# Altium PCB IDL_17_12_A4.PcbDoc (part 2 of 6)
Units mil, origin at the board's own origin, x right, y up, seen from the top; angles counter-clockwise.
Board outline 3172.06 x 10350 mil, 6 copper layers (Top Signal, Mid Signal, 3.3 Volt, GND, 5 Volt, Bot Signal), stack 122.8 mil thick; 332 components, 120 nets, 1937 pads, 197 vias.
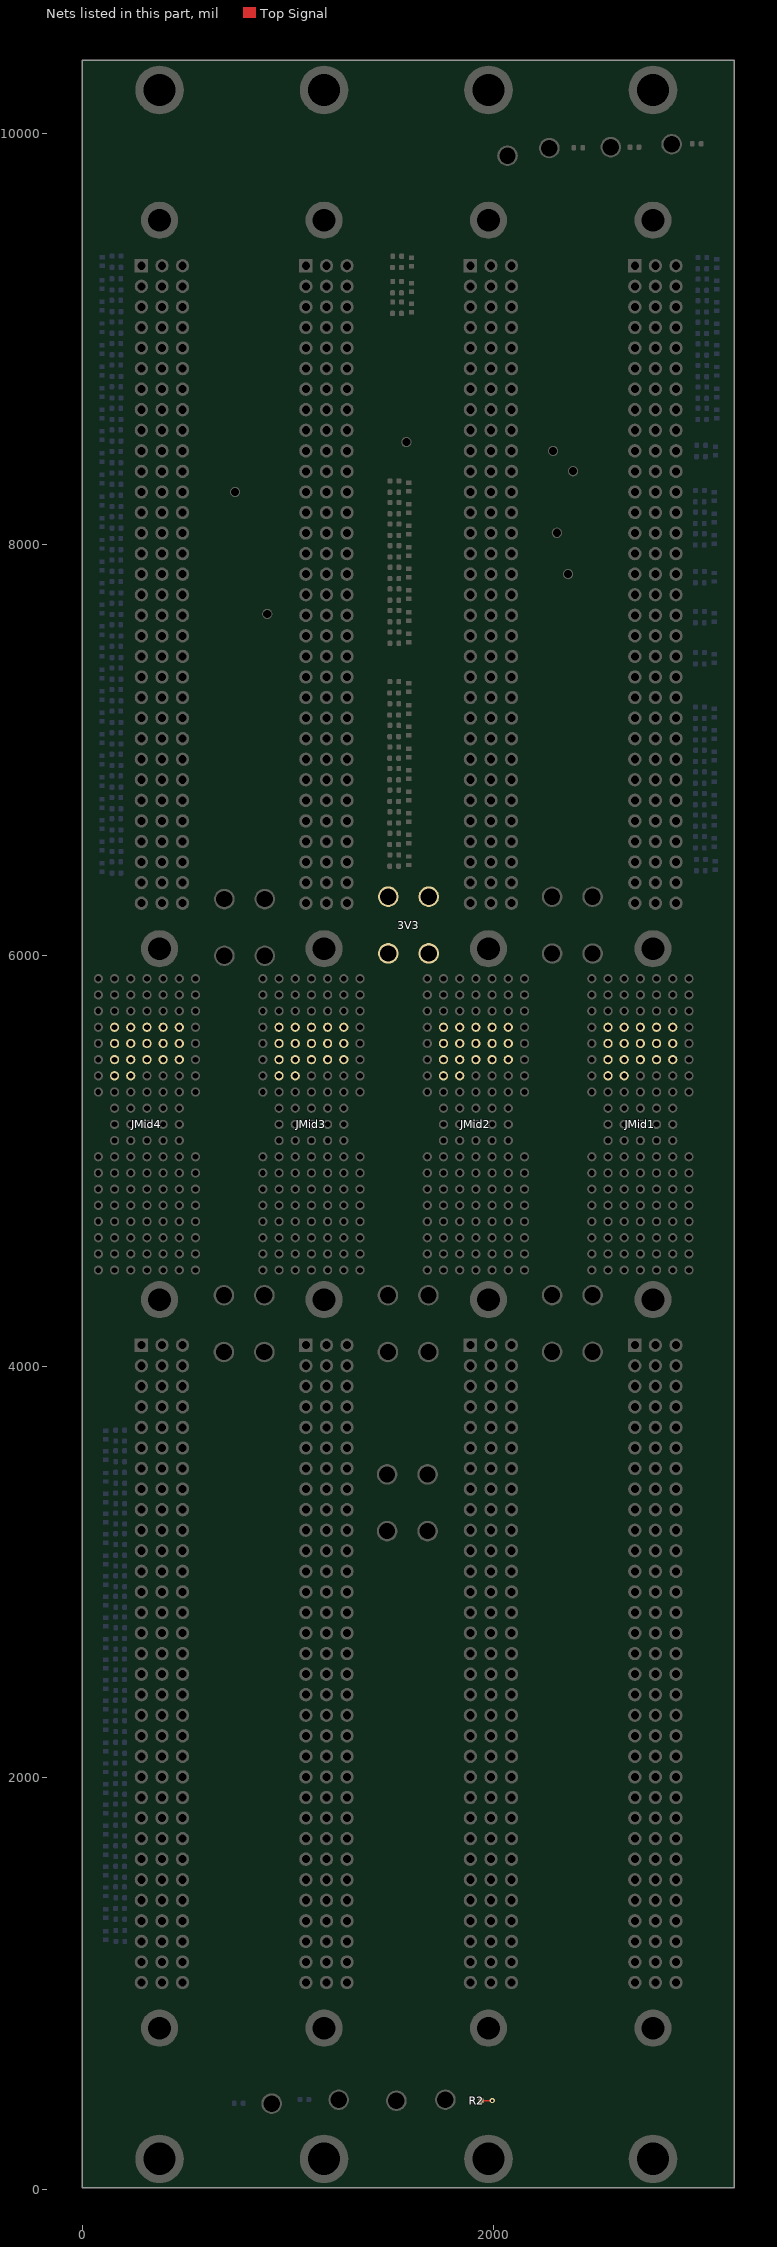
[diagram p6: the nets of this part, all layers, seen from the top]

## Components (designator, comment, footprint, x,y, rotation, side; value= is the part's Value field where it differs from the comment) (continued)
R1R_IDL_17_12_TerA10 "499R" RC0402N1R 3004.11,7618.54 r0 bottom (schematic designator R1R)
R1R_IDL_17_12_TerA11 "499R" RC0402N1R 3004.11,7813.54 r0 bottom (schematic designator R1R)
R1R_IDL_17_12_TerA12 "499R" RC0402N1R 3003.74,7996.75 r0 bottom (schematic designator R1R)
R1R_IDL_17_12_TerA13 "499R" RC0402N1R 3003.74,8101.75 r0 bottom (schematic designator R1R)
R1R_IDL_17_12_TerA14 "499R" RC0402N1R 3003.74,8206.75 r0 bottom (schematic designator R1R)
R1R_IDL_17_12_TerA15 "499R" RC0402N1R 3009.74,8426.69 r0 bottom (schematic designator R1R)
R1R_IDL_17_12_TerA16 "499R" RC0402N1R 3015.45,8607.39 r0 bottom (schematic designator R1R)
R1R_IDL_17_12_TerA17 "499R" RC0402N1R 3015.45,8710.39 r0 bottom (schematic designator R1R)
R1R_IDL_17_12_TerA18 "499R" RC0402N1R 3015.45,8815.39 r0 bottom (schematic designator R1R)
R1R_IDL_17_12_TerA19 "499R" RC0402N1R 3015.45,8920.39 r0 bottom (schematic designator R1R)
R1R_IDL_17_12_TerA20 "499R" RC0402N1R 3015.45,9025.39 r0 bottom (schematic designator R1R)
R1R_IDL_17_12_TerA21 "499R" RC0402N1R 3015.45,9130.39 r0 bottom (schematic designator R1R)
R1R_IDL_17_12_TerA22 "499R" RC0402N1R 3015.45,9235.39 r0 bottom (schematic designator R1R)
R1R_IDL_17_12_TerA23 "499R" RC0402N1R 3015.45,9340.39 r0 bottom (schematic designator R1R)
R1R_IDL_17_12_TerA24 "499R" RC0402N1R 1517.25,6434.64 r0 top (schematic designator R1R)
R1R_IDL_17_12_TerA25 "499R" RC0402N1R 1517.25,6539.64 r0 top (schematic designator R1R)
R1R_IDL_17_12_TerA26 "499R" RC0402N1R 1517.25,6644.64 r0 top (schematic designator R1R)
R1R_IDL_17_12_TerA27 "499R" RC0402N1R 1517.25,6749.64 r0 top (schematic designator R1R)
R1R_IDL_17_12_TerA28 "499R" RC0402N1R 1517.25,6854.64 r0 top (schematic designator R1R)
R1R_IDL_17_12_TerA29 "499R" RC0402N1R 1517.25,6959.64 r0 top (schematic designator R1R)
R1R_IDL_17_12_TerA30 "499R" RC0402N1R 1517.25,7064.64 r0 top (schematic designator R1R)
R1R_IDL_17_12_TerA31 "499R" RC0402N1R 1517.25,7169.64 r0 top (schematic designator R1R)
R1R_IDL_17_12_TerA32 "499R" RC0402N1R 1517.25,7277.64 r0 top (schematic designator R1R)
R1R_IDL_17_12_TerA33 "499R" RC0402N1R 1518.2,7518.53 r0 top (schematic designator R1R)
R1R_IDL_17_12_TerA34 "499R" RC0402N1R 1518.2,7623.53 r0 top (schematic designator R1R)
R1R_IDL_17_12_TerA35 "499R" RC0402N1R 1518.2,7728.53 r0 top (schematic designator R1R)
R1R_IDL_17_12_TerA36 "499R" RC0402N1R 1518.2,7833.53 r0 top (schematic designator R1R)
R1R_IDL_17_12_TerA37 "499R" RC0402N1R 1518.2,7938.53 r0 top (schematic designator R1R)
R1R_IDL_17_12_TerA38 "499R" RC0402N1R 1518.2,8043.53 r0 top (schematic designator R1R)
R1R_IDL_17_12_TerA39 "499R" RC0402N1R 1518.2,8148.53 r0 top (schematic designator R1R)
R1R_IDL_17_12_TerA40 "499R" RC0402N1R 1518.2,8253.53 r0 top (schematic designator R1R)
R1R_IDL_17_12_TerA41 "499R" RC0402N1R 1531.25,9123.5 r0 top (schematic designator R1R)
R1R_IDL_17_12_TerA42 "499R" RC0402N1R 1531.25,9223.5 r0 top (schematic designator R1R)
R1R_IDL_17_12_TerA43 "499R" RC0402N1R 1531.18,9346.47 r0 top (schematic designator R1R)
R1R_IDL_17_12_TerA44 "499R" RC0402N1R 166.72,6400.97 r180 bottom (schematic designator R1R)
R1R_IDL_17_12_TerA45 "499R" RC0402N1R 166.72,6505.97 r180 bottom (schematic designator R1R)
R1R_IDL_17_12_TerA46 "499R" RC0402N1R 166.72,6610.97 r180 bottom (schematic designator R1R)
R1R_IDL_17_12_TerA47 "499R" RC0402N1R 166.72,6713.97 r180 bottom (schematic designator R1R)
R1R_IDL_17_12_TerA48 "499R" RC0402N1R 166.72,6818.97 r180 bottom (schematic designator R1R)
R1R_IDL_17_12_TerA49 "499R" RC0402N1R 166.72,6923.97 r180 bottom (schematic designator R1R)
R1R_IDL_17_12_TerA50 "499R" RC0402N1R 166.72,7028.97 r180 bottom (schematic designator R1R)
R1R_IDL_17_12_TerA51 "499R" RC0402N1R 166.72,7133.97 r180 bottom (schematic designator R1R)
R1R_IDL_17_12_TerA52 "499R" RC0402N1R 166.72,7238.97 r180 bottom (schematic designator R1R)
R1R_IDL_17_12_TerA53 "499R" RC0402N1R 166.72,7343.97 r180 bottom (schematic designator R1R)
R1R_IDL_17_12_TerA54 "499R" RC0402N1R 166.72,7448.97 r180 bottom (schematic designator R1R)
R1R_IDL_17_12_TerA55 "499R" RC0402N1R 166.72,7553.97 r180 bottom (schematic designator R1R)
R1R_IDL_17_12_TerA56 "499R" RC0402N1R 166.72,7658.97 r180 bottom (schematic designator R1R)
R1R_IDL_17_12_TerA57 "499R" RC0402N1R 166.72,7763.97 r180 bottom (schematic designator R1R)
R1R_IDL_17_12_TerA58 "499R" RC0402N1R 166.72,7868.97 r180 bottom (schematic designator R1R)
R1R_IDL_17_12_TerA59 "499R" RC0402N1R 166.72,7973.97 r180 bottom (schematic designator R1R)
R1R_IDL_17_12_TerA60 "499R" RC0402N1R 166.72,8078.97 r180 bottom (schematic designator R1R)
R1R_IDL_17_12_TerA61 "499R" RC0402N1R 166.72,8183.97 r180 bottom (schematic designator R1R)
R1R_IDL_17_12_TerA62 "499R" RC0402N1R 166.72,8291.97 r180 bottom (schematic designator R1R)
R1R_IDL_17_12_TerA63 "499R" RC0402N1R 166.72,8396.97 r180 bottom (schematic designator R1R)
R1R_IDL_17_12_TerA64 "499R" RC0402N1R 166.72,8501.97 r180 bottom (schematic designator R1R)
R1R_IDL_17_12_TerA65 "499R" RC0402N1R 166.72,8606.97 r180 bottom (schematic designator R1R)
R1R_IDL_17_12_TerA66 "499R" RC0402N1R 166.72,8711.97 r180 bottom (schematic designator R1R)
R1R_IDL_17_12_TerA67 "499R" RC0402N1R 166.72,8816.97 r180 bottom (schematic designator R1R)
R1R_IDL_17_12_TerA68 "499R" RC0402N1R 166.72,8921.97 r180 bottom (schematic designator R1R)
R1R_IDL_17_12_TerA69 "499R" RC0402N1R 166.72,9026.97 r180 bottom (schematic designator R1R)
R1R_IDL_17_12_TerA70 "499R" RC0402N1R 166.72,9131.97 r180 bottom (schematic designator R1R)
R1R_IDL_17_12_TerA71 "499R" RC0402N1R 166.72,9236.97 r180 bottom (schematic designator R1R)
R1R_IDL_17_12_TerA72 "499R" RC0402N1R 166.7,9347.52 r180 bottom (schematic designator R1R)
R1RB_IDL_17_12_TerB1 "499R" RC0402N1R 185.61,1204.96 r180 bottom (schematic designator R1RB)
R1RB_IDL_17_12_TerB2 "499R" RC0402N1R 184.91,1312.44 r180 bottom (schematic designator R1RB)
R1RB_IDL_17_12_TerB3 "499R" RC0402N1R 184.91,1417.44 r180 bottom (schematic designator R1RB)
R1RB_IDL_17_12_TerB4 "499R" RC0402N1R 184.91,1517.44 r180 bottom (schematic designator R1RB)
R1RB_IDL_17_12_TerB5 "499R" RC0402N1R 184.91,1617.44 r180 bottom (schematic designator R1RB)
R1RB_IDL_17_12_TerB6 "499R" RC0402N1R 184.91,1717.44 r180 bottom (schematic designator R1RB)
R1RB_IDL_17_12_TerB7 "499R" RC0402N1R 184.91,1820.44 r180 bottom (schematic designator R1RB)
R1RB_IDL_17_12_TerB8 "499R" RC0402N1R 184.91,1920.44 r180 bottom (schematic designator R1RB)
R1RB_IDL_17_12_TerB9 "499R" RC0402N1R 184.91,2020.44 r180 bottom (schematic designator R1RB)
R1RB_IDL_17_12_TerB10 "499R" RC0402N1R 184.91,2120.44 r180 bottom (schematic designator R1RB)
R1RB_IDL_17_12_TerB11 "499R" RC0402N1R 184.91,2225.44 r180 bottom (schematic designator R1RB)
R1RB_IDL_17_12_TerB12 "499R" RC0402N1R 184.91,2325.44 r180 bottom (schematic designator R1RB)
R1RB_IDL_17_12_TerB13 "499R" RC0402N1R 184.91,2425.44 r180 bottom (schematic designator R1RB)
R1RB_IDL_17_12_TerB14 "499R" RC0402N1R 184.91,2525.44 r180 bottom (schematic designator R1RB)
R1RB_IDL_17_12_TerB15 "499R" RC0402N1R 184.91,2625.44 r180 bottom (schematic designator R1RB)
R1RB_IDL_17_12_TerB16 "499R" RC0402N1R 184.91,2730.44 r180 bottom (schematic designator R1RB)
R1RB_IDL_17_12_TerB17 "499R" RC0402N1R 184.91,2830.44 r180 bottom (schematic designator R1RB)
R1RB_IDL_17_12_TerB18 "499R" RC0402N1R 184.91,2930.44 r180 bottom (schematic designator R1RB)
R1RB_IDL_17_12_TerB19 "499R" RC0402N1R 184.91,3030.44 r180 bottom (schematic designator R1RB)
R1RB_IDL_17_12_TerB20 "499R" RC0402N1R 184.91,3135.44 r180 bottom (schematic designator R1RB)
R1RB_IDL_17_12_TerB21 "499R" RC0402N1R 184.91,3235.44 r180 bottom (schematic designator R1RB)
R1RB_IDL_17_12_TerB22 "499R" RC0402N1R 184.91,3333.44 r180 bottom (schematic designator R1RB)
R1RB_IDL_17_12_TerB23 "499R" RC0402N1R 184.91,3433.44 r180 bottom (schematic designator R1RB)
R1RB_IDL_17_12_TerB24 "499R" RC0402N1R 184.91,3538.44 r180 bottom (schematic designator R1RB)
R1RB_IDL_17_12_TerB25 "499R" RC0402N1R 184.91,3638.44 r180 bottom (schematic designator R1RB)
R2 "0R0" RC0402N1R 1918.13,429.92 r0 top
R2R_IDL_17_12_TerA1 "499R" RC0402N1R 3009.98,6467.32 r180 bottom (schematic designator R2R)
R2R_IDL_17_12_TerA2 "499R" RC0402N1R 3004.98,6578.56 r180 bottom (schematic designator R2R)
R2R_IDL_17_12_TerA3 "499R" RC0402N1R 3004.98,6683.56 r180 bottom (schematic designator R2R)
R2R_IDL_17_12_TerA4 "499R" RC0402N1R 3004.98,6788.56 r180 bottom (schematic designator R2R)
R2R_IDL_17_12_TerA5 "499R" RC0402N1R 3004.98,6893.56 r180 bottom (schematic designator R2R)
R2R_IDL_17_12_TerA6 "499R" RC0402N1R 3004.98,6998.56 r180 bottom (schematic designator R2R)
R2R_IDL_17_12_TerA7 "499R" RC0402N1R 3004.98,7103.56 r180 bottom (schematic designator R2R)
R2R_IDL_17_12_TerA8 "499R" RC0402N1R 3004.98,7208.56 r180 bottom (schematic designator R2R)
R2R_IDL_17_12_TerA9 "499R" RC0402N1R 3004.98,7473.56 r180 bottom (schematic designator R2R)
R2R_IDL_17_12_TerA10 "499R" RC0402N1R 3004.98,7673.56 r180 bottom (schematic designator R2R)
R2R_IDL_17_12_TerA11 "499R" RC0402N1R 3004.98,7868.56 r180 bottom (schematic designator R2R)
R2R_IDL_17_12_TerA12 "499R" RC0402N1R 3004.61,8051.77 r180 bottom (schematic designator R2R)
R2R_IDL_17_12_TerA13 "499R" RC0402N1R 3004.61,8156.77 r180 bottom (schematic designator R2R)
R2R_IDL_17_12_TerA14 "499R" RC0402N1R 3004.61,8261.77 r180 bottom (schematic designator R2R)
R2R_IDL_17_12_TerA15 "499R" RC0402N1R 3010.62,8481.71 r180 bottom (schematic designator R2R)
R2R_IDL_17_12_TerA16 "499R" RC0402N1R 3016.32,8662.41 r180 bottom (schematic designator R2R)
R2R_IDL_17_12_TerA17 "499R" RC0402N1R 3016.32,8765.41 r180 bottom (schematic designator R2R)
R2R_IDL_17_12_TerA18 "499R" RC0402N1R 3016.32,8870.41 r180 bottom (schematic designator R2R)
R2R_IDL_17_12_TerA19 "499R" RC0402N1R 3016.32,8975.41 r180 bottom (schematic designator R2R)
R2R_IDL_17_12_TerA20 "499R" RC0402N1R 3016.32,9080.41 r180 bottom (schematic designator R2R)
R2R_IDL_17_12_TerA21 "499R" RC0402N1R 3016.32,9185.41 r180 bottom (schematic designator R2R)
R2R_IDL_17_12_TerA22 "499R" RC0402N1R 3016.32,9290.41 r180 bottom (schematic designator R2R)
R2R_IDL_17_12_TerA23 "499R" RC0402N1R 3016.32,9395.41 r180 bottom (schematic designator R2R)
R2R_IDL_17_12_TerA24 "499R" RC0402N1R 1518.12,6489.66 r180 top (schematic designator R2R)
R2R_IDL_17_12_TerA25 "499R" RC0402N1R 1518.12,6594.66 r180 top (schematic designator R2R)
R2R_IDL_17_12_TerA26 "499R" RC0402N1R 1518.12,6699.66 r180 top (schematic designator R2R)
R2R_IDL_17_12_TerA27 "499R" RC0402N1R 1518.12,6804.66 r180 top (schematic designator R2R)
R2R_IDL_17_12_TerA28 "499R" RC0402N1R 1518.12,6909.66 r180 top (schematic designator R2R)
R2R_IDL_17_12_TerA29 "499R" RC0402N1R 1518.12,7014.66 r180 top (schematic designator R2R)
R2R_IDL_17_12_TerA30 "499R" RC0402N1R 1518.12,7119.66 r180 top (schematic designator R2R)
R2R_IDL_17_12_TerA31 "499R" RC0402N1R 1518.12,7224.66 r180 top (schematic designator R2R)
R2R_IDL_17_12_TerA32 "499R" RC0402N1R 1518.12,7332.66 r180 top (schematic designator R2R)
R2R_IDL_17_12_TerA33 "499R" RC0402N1R 1519.08,7573.55 r180 top (schematic designator R2R)
R2R_IDL_17_12_TerA34 "499R" RC0402N1R 1519.08,7678.55 r180 top (schematic designator R2R)
R2R_IDL_17_12_TerA35 "499R" RC0402N1R 1519.08,7783.55 r180 top (schematic designator R2R)
R2R_IDL_17_12_TerA36 "499R" RC0402N1R 1519.08,7888.55 r180 top (schematic designator R2R)
R2R_IDL_17_12_TerA37 "499R" RC0402N1R 1519.08,7993.55 r180 top (schematic designator R2R)
R2R_IDL_17_12_TerA38 "499R" RC0402N1R 1519.08,8098.55 r180 top (schematic designator R2R)
R2R_IDL_17_12_TerA39 "499R" RC0402N1R 1519.08,8203.55 r180 top (schematic designator R2R)
R2R_IDL_17_12_TerA40 "499R" RC0402N1R 1519.08,8308.55 r180 top (schematic designator R2R)
R2R_IDL_17_12_TerA41 "499R" RC0402N1R 1532.12,9178.52 r180 top (schematic designator R2R)
R2R_IDL_17_12_TerA42 "499R" RC0402N1R 1532.12,9278.52 r180 top (schematic designator R2R)
R2R_IDL_17_12_TerA43 "499R" RC0402N1R 1532.05,9401.49 r180 top (schematic designator R2R)
R2R_IDL_17_12_TerA44 "499R" RC0402N1R 165.84,6455.99 r0 bottom (schematic designator R2R)
R2R_IDL_17_12_TerA45 "499R" RC0402N1R 165.84,6560.99 r0 bottom (schematic designator R2R)
R2R_IDL_17_12_TerA46 "499R" RC0402N1R 165.84,6665.99 r0 bottom (schematic designator R2R)
R2R_IDL_17_12_TerA47 "499R" RC0402N1R 165.84,6768.99 r0 bottom (schematic designator R2R)
R2R_IDL_17_12_TerA48 "499R" RC0402N1R 165.84,6873.99 r0 bottom (schematic designator R2R)
R2R_IDL_17_12_TerA49 "499R" RC0402N1R 165.84,6978.99 r0 bottom (schematic designator R2R)
R2R_IDL_17_12_TerA50 "499R" RC0402N1R 165.84,7083.99 r0 bottom (schematic designator R2R)
R2R_IDL_17_12_TerA51 "499R" RC0402N1R 165.84,7188.99 r0 bottom (schematic designator R2R)
R2R_IDL_17_12_TerA52 "499R" RC0402N1R 165.84,7293.99 r0 bottom (schematic designator R2R)
R2R_IDL_17_12_TerA53 "499R" RC0402N1R 165.84,7398.99 r0 bottom (schematic designator R2R)
R2R_IDL_17_12_TerA54 "499R" RC0402N1R 165.84,7503.99 r0 bottom (schematic designator R2R)
R2R_IDL_17_12_TerA55 "499R" RC0402N1R 165.84,7608.99 r0 bottom (schematic designator R2R)
R2R_IDL_17_12_TerA56 "499R" RC0402N1R 165.84,7713.99 r0 bottom (schematic designator R2R)
R2R_IDL_17_12_TerA57 "499R" RC0402N1R 165.84,7818.99 r0 bottom (schematic designator R2R)
R2R_IDL_17_12_TerA58 "499R" RC0402N1R 165.84,7923.99 r0 bottom (schematic designator R2R)
R2R_IDL_17_12_TerA59 "499R" RC0402N1R 165.84,8028.99 r0 bottom (schematic designator R2R)
R2R_IDL_17_12_TerA60 "499R" RC0402N1R 165.84,8133.99 r0 bottom (schematic designator R2R)
R2R_IDL_17_12_TerA61 "499R" RC0402N1R 165.84,8238.99 r0 bottom (schematic designator R2R)
R2R_IDL_17_12_TerA62 "499R" RC0402N1R 165.84,8346.99 r0 bottom (schematic designator R2R)
R2R_IDL_17_12_TerA63 "499R" RC0402N1R 165.84,8451.99 r0 bottom (schematic designator R2R)
R2R_IDL_17_12_TerA64 "499R" RC0402N1R 165.84,8556.99 r0 bottom (schematic designator R2R)
R2R_IDL_17_12_TerA65 "499R" RC0402N1R 165.84,8661.99 r0 bottom (schematic designator R2R)
R2R_IDL_17_12_TerA66 "499R" RC0402N1R 165.84,8766.99 r0 bottom (schematic designator R2R)
R2R_IDL_17_12_TerA67 "499R" RC0402N1R 165.84,8871.99 r0 bottom (schematic designator R2R)
R2R_IDL_17_12_TerA68 "499R" RC0402N1R 165.84,8976.99 r0 bottom (schematic designator R2R)
R2R_IDL_17_12_TerA69 "499R" RC0402N1R 165.84,9081.99 r0 bottom (schematic designator R2R)
R2R_IDL_17_12_TerA70 "499R" RC0402N1R 165.84,9186.99 r0 bottom (schematic designator R2R)
R2R_IDL_17_12_TerA71 "499R" RC0402N1R 165.84,9291.99 r0 bottom (schematic designator R2R)
R2R_IDL_17_12_TerA72 "499R" RC0402N1R 166.97,9402.03 r0 bottom (schematic designator R2R)
R2RB_IDL_17_12_TerB1 "499R" RC0402N1R 185.09,1257.82 r0 bottom (schematic designator R2RB)
R2RB_IDL_17_12_TerB2 "499R" RC0402N1R 184.4,1365.3 r0 bottom (schematic designator R2RB)
R2RB_IDL_17_12_TerB3 "499R" RC0402N1R 184.4,1470.3 r0 bottom (schematic designator R2RB)
R2RB_IDL_17_12_TerB4 "499R" RC0402N1R 184.4,1570.3 r0 bottom (schematic designator R2RB)
R2RB_IDL_17_12_TerB5 "499R" RC0402N1R 184.4,1670.3 r0 bottom (schematic designator R2RB)
R2RB_IDL_17_12_TerB6 "499R" RC0402N1R 184.4,1770.3 r0 bottom (schematic designator R2RB)
R2RB_IDL_17_12_TerB7 "499R" RC0402N1R 184.4,1873.3 r0 bottom (schematic designator R2RB)
R2RB_IDL_17_12_TerB8 "499R" RC0402N1R 184.4,1973.3 r0 bottom (schematic designator R2RB)
R2RB_IDL_17_12_TerB9 "499R" RC0402N1R 184.4,2073.3 r0 bottom (schematic designator R2RB)
R2RB_IDL_17_12_TerB10 "499R" RC0402N1R 184.4,2173.3 r0 bottom (schematic designator R2RB)
R2RB_IDL_17_12_TerB11 "499R" RC0402N1R 184.4,2278.3 r0 bottom (schematic designator R2RB)
R2RB_IDL_17_12_TerB12 "499R" RC0402N1R 184.4,2378.3 r0 bottom (schematic designator R2RB)
R2RB_IDL_17_12_TerB13 "499R" RC0402N1R 184.4,2478.3 r0 bottom (schematic designator R2RB)
R2RB_IDL_17_12_TerB14 "499R" RC0402N1R 184.4,2578.3 r0 bottom (schematic designator R2RB)
R2RB_IDL_17_12_TerB15 "499R" RC0402N1R 184.4,2678.3 r0 bottom (schematic designator R2RB)
R2RB_IDL_17_12_TerB16 "499R" RC0402N1R 184.4,2783.3 r0 bottom (schematic designator R2RB)
R2RB_IDL_17_12_TerB17 "499R" RC0402N1R 184.4,2883.3 r0 bottom (schematic designator R2RB)
R2RB_IDL_17_12_TerB18 "499R" RC0402N1R 184.4,2983.3 r0 bottom (schematic designator R2RB)
R2RB_IDL_17_12_TerB19 "499R" RC0402N1R 184.4,3083.3 r0 bottom (schematic designator R2RB)
R2RB_IDL_17_12_TerB20 "499R" RC0402N1R 184.4,3188.3 r0 bottom (schematic designator R2RB)
R2RB_IDL_17_12_TerB21 "499R" RC0402N1R 184.4,3288.3 r0 bottom (schematic designator R2RB)
R2RB_IDL_17_12_TerB22 "499R" RC0402N1R 184.4,3386.3 r0 bottom (schematic designator R2RB)
R2RB_IDL_17_12_TerB23 "499R" RC0402N1R 184.4,3486.3 r0 bottom (schematic designator R2RB)
R2RB_IDL_17_12_TerB24 "499R" RC0402N1R 184.4,3591.3 r0 bottom (schematic designator R2RB)
R2RB_IDL_17_12_TerB25 "499R" RC0402N1R 184.4,3691.3 r0 bottom (schematic designator R2RB)
R3 "0R0" RC0402N1R 2988.92,9948.74 r0 top
R4 "0R0" RC0402N1R 761.24,417.54 r180 bottom
R5 "0R0" RC0402N1R 2412.86,9929.14 r0 top
R6 "0R0" RC0402N1R 1080.79,436.23 r180 bottom
SYSCLK "Comment" TPH0.5S#3 1576.8,8497.37 r0 bottom
SYSFAIL "Comment" TPH0.5S#3 2290.4,8454.36 r180 bottom
SYSRESET "Comment" TPH0.5S#3 743.75,8254.74 r180 bottom
WRITE "Comment" TPH0.5S#3 2308.92,8056.34 r180 bottom

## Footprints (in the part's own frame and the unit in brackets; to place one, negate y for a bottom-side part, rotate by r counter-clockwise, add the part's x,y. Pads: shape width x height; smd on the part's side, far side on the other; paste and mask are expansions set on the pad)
"127-Pin Conncector" [mil] "Har-Bus male connector type AB-19"
  round 45 hole 27.56: 1(-732.28,-240.16) 2(-653.54,-240.16) 3(-574.8,-240.16) 4(-496.06,-240.16) 5(-417.32,-240.16) 6(-338.58,-240.16) 7(-259.84,-240.16) 8(-181.1,-240.16) 9(133.86,-240.16) 10(212.6,-240.16) 11(291.34,-240.16) 12(370.08,-240.16) 13(448.82,-240.16) 14(527.56,-240.16) 15(606.3,-240.16) 16(685.04,-240.16) 17(-732.28,-161.42) 18(-653.54,-161.42) 19(-574.8,-161.42) 20(-496.06,-161.42) 21(-417.32,-161.42) 22(-338.58,-161.42) 23(-259.84,-161.42) 24(-181.1,-161.42) 25(-102.36,-161.42) 26(-23.62,-161.42) 27(55.12,-161.42) 28(133.86,-161.42) 29(212.6,-161.42) 30(291.34,-161.42) 31(370.08,-161.42) 32(448.82,-161.42) 33(527.56,-161.42) 34(606.3,-161.42) 35(685.04,-161.42) 36(-732.28,-82.68) 37(-653.54,-82.68) 38(-574.8,-82.68) 39(-496.06,-82.68) 40(-417.32,-82.68) 41(-338.58,-82.68) 42(-259.84,-82.68) 43(-181.1,-82.68) 44(-102.36,-82.68) 45(-23.62,-82.68) 46(55.12,-82.68) 47(133.86,-82.68) 48(212.6,-82.68) 49(291.34,-82.68) 50(370.08,-82.68) 51(448.82,-82.68) 52(527.56,-82.68) 53(606.3,-82.68) 54(685.04,-82.68) 55(-732.28,-3.94) 56(-653.54,-3.94) 57(-574.8,-3.94) 58(-496.06,-3.94) 59(-417.32,-3.94) 60(-338.58,-3.94) 61(-259.84,-3.94) 62(-181.1,-3.94) 63(-102.36,-3.94) 64(-23.62,-3.94) 65(55.12,-3.94) 66(133.86,-3.94) 67(212.6,-3.94) 68(291.34,-3.94) 69(370.08,-3.94) 70(448.82,-3.94) 71(527.56,-3.94) 72(606.3,-3.94) 73(685.04,-3.94) 74(-732.28,74.8) 75(-653.54,74.8) 76(-574.8,74.8) 77(-496.06,74.8) 78(-417.32,74.8) 79(-338.58,74.8) 80(-259.84,74.8) 81(-181.1,74.8) 82(-102.36,74.8) 83(-23.62,74.8) 84(55.12,74.8) 85(133.86,74.8) 86(212.6,74.8) 87(291.34,74.8) 88(370.08,74.8) 89(448.82,74.8) 90(527.56,74.8) 91(606.3,74.8) 92(685.04,74.8) 93(-732.28,153.54) 94(-653.54,153.54) 95(-574.8,153.54) 96(-496.06,153.54) 97(-417.32,153.54) 98(-338.58,153.54) 99(-259.84,153.54) 100(-181.1,153.54) 101(-102.36,153.54) 102(-23.62,153.54) 103(55.12,153.54) 104(133.86,153.54) 105(212.6,153.54) 106(291.34,153.54) 107(370.08,153.54) 108(448.82,153.54) 109(527.56,153.54) 110(606.3,153.54) 111(685.04,153.54) 112(-732.28,232.28) 113(-653.54,232.28) 114(-574.8,232.28) 115(-496.06,232.28) 116(-417.32,232.28) 117(-338.58,232.28) 118(-259.84,232.28) 119(-181.1,232.28) 120(133.86,232.28) 121(212.6,232.28) 122(291.34,232.28) 123(370.08,232.28) 124(448.82,232.28) 125(527.56,232.28) 126(606.3,232.28) 127(685.04,232.28)
  silkscreen extent -772,-307 724,299, body extent -732,-276 685,276, height 528
0903296x825 [mm] "Connector; DIN 41612, Type C, Thru-Hole; Rows a+b+c, 96 Position; Vertical"
  round 4.6 hole 2.8: 33(-45,-0.3) 34(45,-0.3)
  rect 1.65x1.65 hole 1: A1(-39.37,-2.54)
  round 1.65 hole 1: A2(-36.83,-2.54) A3(-34.29,-2.54) A4(-31.75,-2.54) A5(-29.21,-2.54) A6(-26.67,-2.54) A7(-24.13,-2.54) A8(-21.59,-2.54) A9(-19.05,-2.54) A10(-16.51,-2.54) A11(-13.97,-2.54) A12(-11.43,-2.54) A13(-8.89,-2.54) A14(-6.35,-2.54) A15(-3.81,-2.54) A16(-1.27,-2.54) A17(1.27,-2.54) A18(3.81,-2.54) A19(6.35,-2.54) A20(8.89,-2.54) A21(11.43,-2.54) A22(13.97,-2.54) A23(16.51,-2.54) A24(19.05,-2.54) A25(21.59,-2.54) A26(24.13,-2.54) A27(26.67,-2.54) A28(29.21,-2.54) A29(31.75,-2.54) A30(34.29,-2.54) A31(36.83,-2.54) A32(39.37,-2.54) B1(-39.37,0) B2(-36.83,0) B3(-34.29,0) B4(-31.75,0) B5(-29.21,0) B6(-26.67,0) B7(-24.13,0) B8(-21.59,0) B9(-19.05,0) B10(-16.51,0) B11(-13.97,0) B12(-11.43,0) B13(-8.89,0) B14(-6.35,0) B15(-3.81,0) B16(-1.27,0) B17(1.27,0) B18(3.81,0) B19(6.35,0) B20(8.89,0) B21(11.43,0) B22(13.97,0) B23(16.51,0) B24(19.05,0) B25(21.59,0) B26(24.13,0) B27(26.67,0) B28(29.21,0) B29(31.75,0) B30(34.29,0) B31(36.83,0) B32(39.37,0) C1(-39.37,2.54) C2(-36.83,2.54) C3(-34.29,2.54) C4(-31.75,2.54) C5(-29.21,2.54) C6(-26.67,2.54) C7(-24.13,2.54) C8(-21.59,2.54) C9(-19.05,2.54) C10(-16.51,2.54) C11(-13.97,2.54) C12(-11.43,2.54) C13(-8.89,2.54) C14(-6.35,2.54) C15(-3.81,2.54) C16(-1.27,2.54) C17(1.27,2.54) C18(3.81,2.54) C19(6.35,2.54) C20(8.89,2.54) C21(11.43,2.54) C22(13.97,2.54) C23(16.51,2.54) C24(19.05,2.54) C25(21.59,2.54) C26(24.13,2.54) C27(26.67,2.54) C28(29.21,2.54) C29(31.75,2.54) C30(34.29,2.54) C31(36.83,2.54) C32(39.37,2.54)
  silkscreen extent -47.5,-5.55 47.5,5.55
CC0402N1X [mm] "Chip capacitor 0402"
  rect 0.55x0.65 smd mask+0.025: 1(-0.525,0) 2(0.525,0)
  silkscreen extent 0,-0.25 0,0.25, body extent -0.51,-0.25 0.51,0.25, height 0.5
PCBComponent_1 [mm]
  round 2.54 hole 2: 1(0,0) 2(5,0) 3(0,-7.01) 4(5,-7.01)
RC0402N1R [mm] "Chip capacitor 0402 ROUNDED PAD"
  rrect50% 0.6x0.65 smd: 1(-0.55,0) 2(0.55,0)
  silkscreen extent 0,-0.25 0,0.25, body extent -0.51,-0.25 0.51,0.25, height 0.36
TPH0.5S#1 [mil] "Test point TH 0.5mm slim"
  round 100 hole 80: 1(0,0)
TPH0.5S#2 [mil] "Test point TH 0.5mm slim"
TPH0.5S#3 [mil] "Test point TH 0.5mm slim"
  round 50 hole 39.37: 1(0,0)
  silkscreen extent -50,-50 50,50
TPH0.5S#4 [mil] "Test point TH 0.5mm slim"
  round 50 hole 39.37: 1(-0.17,0.01)
  silkscreen extent -50,-50 50,50
TPH0.5S#5 [mil] "Test point TH 0.5mm slim"
  round 100 hole 80: 1(-0.53,0.37)

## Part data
3V3 5V 12V -3V3 -5V -12V GND: library part Component_1, "TERM SCREW 6-32 4 PIN PCB"
3V3 5V 12V -3V3 -5V -12V -12V: library part ELE-TP0.5S, "Test Point 0.5mm Slim"
CR_IDL_17_12_TerA1 CR_IDL_17_12_TerA2 CR_IDL_17_12_TerA3 CR_IDL_17_12_TerA4 CR_IDL_17_12_TerA5 CR_IDL_17_12_TerA6 CR_IDL_17_12_TerA7 CR_IDL_17_12_TerA8 CR_IDL_17_12_TerA9 CR_IDL_17_12_TerA10 CR_IDL_17_12_TerA11 CR_IDL_17_12_TerA12 CR_IDL_17_12_TerA13 CR_IDL_17_12_TerA14 CR_IDL_17_12_TerA15 CR_IDL_17_12_TerA16 CR_IDL_17_12_TerA17 CR_IDL_17_12_TerA18 CR_IDL_17_12_TerA19 CR_IDL_17_12_TerA20 CR_IDL_17_12_TerA21 CR_IDL_17_12_TerA22 CR_IDL_17_12_TerA23 CR_IDL_17_12_TerA24 CR_IDL_17_12_TerA25 CR_IDL_17_12_TerA26 CR_IDL_17_12_TerA27 CR_IDL_17_12_TerA28 CR_IDL_17_12_TerA29 CR_IDL_17_12_TerA30 CR_IDL_17_12_TerA31 CR_IDL_17_12_TerA32 CR_IDL_17_12_TerA33 CR_IDL_17_12_TerA34 CR_IDL_17_12_TerA35 CR_IDL_17_12_TerA36 CR_IDL_17_12_TerA37 CR_IDL_17_12_TerA38 CR_IDL_17_12_TerA39 CR_IDL_17_12_TerA40 CR_IDL_17_12_TerA41 CR_IDL_17_12_TerA42 CR_IDL_17_12_TerA43 CR_IDL_17_12_TerA44 CR_IDL_17_12_TerA45 CR_IDL_17_12_TerA46 CR_IDL_17_12_TerA47 CR_IDL_17_12_TerA48 CR_IDL_17_12_TerA49 CR_IDL_17_12_TerA50 CR_IDL_17_12_TerA51 CR_IDL_17_12_TerA52 CR_IDL_17_12_TerA53 CR_IDL_17_12_TerA54 CR_IDL_17_12_TerA55 CR_IDL_17_12_TerA56 CR_IDL_17_12_TerA57 CR_IDL_17_12_TerA58 CR_IDL_17_12_TerA59 CR_IDL_17_12_TerA60 CR_IDL_17_12_TerA61 CR_IDL_17_12_TerA62 CR_IDL_17_12_TerA63 CR_IDL_17_12_TerA64 CR_IDL_17_12_TerA65 CR_IDL_17_12_TerA66 CR_IDL_17_12_TerA67 CR_IDL_17_12_TerA68 CR_IDL_17_12_TerA69 CR_IDL_17_12_TerA70 CR_IDL_17_12_TerA71 CR_IDL_17_12_TerA72 CRB_IDL_17_12_TerB1 CRB_IDL_17_12_TerB2 CRB_IDL_17_12_TerB3 CRB_IDL_17_12_TerB4 CRB_IDL_17_12_TerB5 CRB_IDL_17_12_TerB6 CRB_IDL_17_12_TerB7 CRB_IDL_17_12_TerB8 CRB_IDL_17_12_TerB9 CRB_IDL_17_12_TerB10 CRB_IDL_17_12_TerB11 CRB_IDL_17_12_TerB12 CRB_IDL_17_12_TerB13 CRB_IDL_17_12_TerB14 CRB_IDL_17_12_TerB15 CRB_IDL_17_12_TerB16 CRB_IDL_17_12_TerB17 CRB_IDL_17_12_TerB18 CRB_IDL_17_12_TerB19 CRB_IDL_17_12_TerB20 CRB_IDL_17_12_TerB21 CRB_IDL_17_12_TerB22 CRB_IDL_17_12_TerB23 CRB_IDL_17_12_TerB24 CRB_IDL_17_12_TerB25: library part CAPCC0402_2_1.0U_50VX7R, "Capacitor chip ceramic 0402 6.3V X7R", Manufacturer=TDK, Manufacturer No=GRM155R70J105KA12D, Package="Cap Chip 0402", Supplier Part Number 1=81-GRM155R70J105KA2D, Voltage rating=6.3V
Jbot1 Jbot2 Jbot3 Jbot4 Jtop1 Jtop2 Jtop3 Jtop4: library part "09 03 296 2825", "Eurocard DIN 41612, Type C, 96 Position, Rows a+b+c, Performance level 1, Female, Lead 4.5 mm, Pitch 2.54 mm", PackageDocument=21-Feb-2002
JMid1 JMid2 JMid3 JMid4: library part "127-pin connector", "127-pin connector", Part No.=17131271201, Supplier Part Number 1=1195-5281-ND
R1 R2 R3 R4 R5 R6: library part RES0402-0-0R-1%100PPM, "Chip Resistor 0402 62.5mW 1% 100ppm", Manufacturer=Panasonic, Manufacturer No=ERJ-2GE0R00X, Package="Res Chip 0402", Supplier Part Number 1=P0.0JCT-ND
R1R_IDL_17_12_TerA1 R1R_IDL_17_12_TerA2 R1R_IDL_17_12_TerA3 R1R_IDL_17_12_TerA4 R1R_IDL_17_12_TerA5 R1R_IDL_17_12_TerA6 R1R_IDL_17_12_TerA7 R1R_IDL_17_12_TerA8 R1R_IDL_17_12_TerA9 R1R_IDL_17_12_TerA10 R1R_IDL_17_12_TerA11 R1R_IDL_17_12_TerA12 R1R_IDL_17_12_TerA13 R1R_IDL_17_12_TerA14 R1R_IDL_17_12_TerA15 R1R_IDL_17_12_TerA16 R1R_IDL_17_12_TerA17 R1R_IDL_17_12_TerA18 R1R_IDL_17_12_TerA19 R1R_IDL_17_12_TerA20 R1R_IDL_17_12_TerA21 R1R_IDL_17_12_TerA22 R1R_IDL_17_12_TerA23 R1R_IDL_17_12_TerA24 R1R_IDL_17_12_TerA25 R1R_IDL_17_12_TerA26 R1R_IDL_17_12_TerA27 R1R_IDL_17_12_TerA28 R1R_IDL_17_12_TerA29 R1R_IDL_17_12_TerA30 R1R_IDL_17_12_TerA31 R1R_IDL_17_12_TerA32 R1R_IDL_17_12_TerA33 R1R_IDL_17_12_TerA34 R1R_IDL_17_12_TerA35 R1R_IDL_17_12_TerA36 R1R_IDL_17_12_TerA37 R1R_IDL_17_12_TerA38 R1R_IDL_17_12_TerA39 R1R_IDL_17_12_TerA40 R1R_IDL_17_12_TerA41 R1R_IDL_17_12_TerA42 R1R_IDL_17_12_TerA43 R1R_IDL_17_12_TerA44 R1R_IDL_17_12_TerA45 R1R_IDL_17_12_TerA46 R1R_IDL_17_12_TerA47 R1R_IDL_17_12_TerA48 R1R_IDL_17_12_TerA49 R1R_IDL_17_12_TerA50 R1R_IDL_17_12_TerA51 R1R_IDL_17_12_TerA52 R1R_IDL_17_12_TerA53 R1R_IDL_17_12_TerA54 R1R_IDL_17_12_TerA55 R1R_IDL_17_12_TerA56 R1R_IDL_17_12_TerA57 R1R_IDL_17_12_TerA58 R1R_IDL_17_12_TerA59 R1R_IDL_17_12_TerA60 R1R_IDL_17_12_TerA61 R1R_IDL_17_12_TerA62 R1R_IDL_17_12_TerA63 R1R_IDL_17_12_TerA64 R1R_IDL_17_12_TerA65 R1R_IDL_17_12_TerA66 R1R_IDL_17_12_TerA67 R1R_IDL_17_12_TerA68 R1R_IDL_17_12_TerA69 R1R_IDL_17_12_TerA70 R1R_IDL_17_12_TerA71 R1R_IDL_17_12_TerA72 R1RB_IDL_17_12_TerB1 R1RB_IDL_17_12_TerB2 R1RB_IDL_17_12_TerB3 R1RB_IDL_17_12_TerB4 R1RB_IDL_17_12_TerB5 R1RB_IDL_17_12_TerB6 R1RB_IDL_17_12_TerB7 R1RB_IDL_17_12_TerB8 R1RB_IDL_17_12_TerB9 R1RB_IDL_17_12_TerB10 R1RB_IDL_17_12_TerB11 R1RB_IDL_17_12_TerB12 R1RB_IDL_17_12_TerB13 R1RB_IDL_17_12_TerB14 R1RB_IDL_17_12_TerB15 R1RB_IDL_17_12_TerB16 R1RB_IDL_17_12_TerB17 R1RB_IDL_17_12_TerB18 R1RB_IDL_17_12_TerB19 R1RB_IDL_17_12_TerB20 R1RB_IDL_17_12_TerB21 R1RB_IDL_17_12_TerB22 R1RB_IDL_17_12_TerB23 R1RB_IDL_17_12_TerB24 R1RB_IDL_17_12_TerB25 R2R_IDL_17_12_TerA1 R2R_IDL_17_12_TerA2 R2R_IDL_17_12_TerA3 R2R_IDL_17_12_TerA4 R2R_IDL_17_12_TerA5 R2R_IDL_17_12_TerA6 R2R_IDL_17_12_TerA7 R2R_IDL_17_12_TerA8 R2R_IDL_17_12_TerA9 R2R_IDL_17_12_TerA10 R2R_IDL_17_12_TerA11 R2R_IDL_17_12_TerA12 R2R_IDL_17_12_TerA13 R2R_IDL_17_12_TerA14 R2R_IDL_17_12_TerA15 R2R_IDL_17_12_TerA16 R2R_IDL_17_12_TerA17 R2R_IDL_17_12_TerA18 R2R_IDL_17_12_TerA19 R2R_IDL_17_12_TerA20 R2R_IDL_17_12_TerA21 R2R_IDL_17_12_TerA22 R2R_IDL_17_12_TerA23 R2R_IDL_17_12_TerA24 R2R_IDL_17_12_TerA25 R2R_IDL_17_12_TerA26 R2R_IDL_17_12_TerA27 R2R_IDL_17_12_TerA28 R2R_IDL_17_12_TerA29 R2R_IDL_17_12_TerA30 R2R_IDL_17_12_TerA31 R2R_IDL_17_12_TerA32 R2R_IDL_17_12_TerA33 R2R_IDL_17_12_TerA34 R2R_IDL_17_12_TerA35 R2R_IDL_17_12_TerA36 R2R_IDL_17_12_TerA37 R2R_IDL_17_12_TerA38 R2R_IDL_17_12_TerA39 R2R_IDL_17_12_TerA40 R2R_IDL_17_12_TerA41 R2R_IDL_17_12_TerA42 R2R_IDL_17_12_TerA43 R2R_IDL_17_12_TerA44 R2R_IDL_17_12_TerA45 R2R_IDL_17_12_TerA46 R2R_IDL_17_12_TerA47 R2R_IDL_17_12_TerA48 R2R_IDL_17_12_TerA49 R2R_IDL_17_12_TerA50 R2R_IDL_17_12_TerA51 R2R_IDL_17_12_TerA52 R2R_IDL_17_12_TerA53 R2R_IDL_17_12_TerA54 R2R_IDL_17_12_TerA55 R2R_IDL_17_12_TerA56 R2R_IDL_17_12_TerA57 R2R_IDL_17_12_TerA58 R2R_IDL_17_12_TerA59 R2R_IDL_17_12_TerA60 R2R_IDL_17_12_TerA61 R2R_IDL_17_12_TerA62 R2R_IDL_17_12_TerA63 R2R_IDL_17_12_TerA64 R2R_IDL_17_12_TerA65 R2R_IDL_17_12_TerA66 R2R_IDL_17_12_TerA67 R2R_IDL_17_12_TerA68 R2R_IDL_17_12_TerA69 R2R_IDL_17_12_TerA70 R2R_IDL_17_12_TerA71 R2R_IDL_17_12_TerA72 R2RB_IDL_17_12_TerB1 R2RB_IDL_17_12_TerB2 R2RB_IDL_17_12_TerB3 R2RB_IDL_17_12_TerB4 R2RB_IDL_17_12_TerB5 R2RB_IDL_17_12_TerB6 R2RB_IDL_17_12_TerB7 R2RB_IDL_17_12_TerB8 R2RB_IDL_17_12_TerB9 R2RB_IDL_17_12_TerB10 R2RB_IDL_17_12_TerB11 R2RB_IDL_17_12_TerB12 R2RB_IDL_17_12_TerB13 R2RB_IDL_17_12_TerB14 R2RB_IDL_17_12_TerB15 R2RB_IDL_17_12_TerB16 R2RB_IDL_17_12_TerB17 R2RB_IDL_17_12_TerB18 R2RB_IDL_17_12_TerB19 R2RB_IDL_17_12_TerB20 R2RB_IDL_17_12_TerB21 R2RB_IDL_17_12_TerB22 R2RB_IDL_17_12_TerB23 R2RB_IDL_17_12_TerB24 R2RB_IDL_17_12_TerB25: library part RES0402-0-499R-1%100PPM, "Chip Resistor 0402 62.5mW 1% 100ppm", Manufacturer=Panasonic, Manufacturer No=ERJ-2RKF4990X, Package="Res Chip 0402", Supplier Part Number 1=P499LDKR-ND

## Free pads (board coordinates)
  round 236.22 hole 157: M3(376.35,147.36) M3(376.35,10210.1) M3(1176.35,147.36) M3(1176.35,10210.1) M3(1976.35,147.36) M3(1976.35,10210.1) M3(2776.35,147.36) M3(2776.35,10210.1)

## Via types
v1: diameter 25.59, hole 12, Top Signal to Bot Signal, 197 vias

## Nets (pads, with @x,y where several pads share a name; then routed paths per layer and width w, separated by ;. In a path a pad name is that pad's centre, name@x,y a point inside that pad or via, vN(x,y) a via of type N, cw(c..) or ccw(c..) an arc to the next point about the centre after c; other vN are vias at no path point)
3V3: 3V3.1@1488.84,6286.44 3V3.2 3V3.3 3V3.4 JMid1.20 JMid1.21 JMid1.22 JMid1.23 JMid1.39 JMid1.40 JMid1.41 JMid1.42 JMid1.58 JMid1.59 JMid1.60 JMid1.77 JMid1.78 JMid1.79 JMid1.96 JMid1.97 JMid1.98 JMid2.20 JMid2.21 JMid2.22 JMid2.23 JMid2.39 JMid2.40 JMid2.41 JMid2.42 JMid2.58 JMid2.59 JMid2.60 JMid2.77 JMid2.78 JMid2.79 JMid2.96 JMid2.97 JMid2.98 JMid3.20 JMid3.21 JMid3.22 JMid3.23 JMid3.39 JMid3.40 JMid3.41 JMid3.42 JMid3.58 JMid3.59 JMid3.60 JMid3.77 JMid3.78 JMid3.79 JMid3.96 JMid3.97 JMid3.98 JMid4.20 JMid4.21 JMid4.22 JMid4.23 JMid4.39 JMid4.40 JMid4.41 JMid4.42 JMid4.58 JMid4.59 JMid4.60 JMid4.77 JMid4.78 JMid4.79 JMid4.96 JMid4.97 JMid4.98 R2.2 | length 55
  Top Signal w8: R2.2@1939.78,429.92 v1@1994.35,429.92 ; v1@1994.36,429.92 v1@1994.66,430.21
  other v1: 1994.35,430.83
